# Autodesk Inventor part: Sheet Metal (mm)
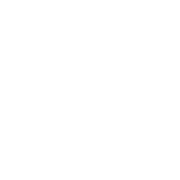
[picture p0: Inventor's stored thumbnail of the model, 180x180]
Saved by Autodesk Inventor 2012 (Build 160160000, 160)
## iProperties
Shininess: 64.0
Length Units: 11269
Angle Units: 11279
Time Units: 11290
Mass Units: 11283
Length Display Precision: 3
Angle Display Precision: 2
Compacted: True
Part Number: Sheet Metal (mm)
Document SubType Name: Sheet Metal
Created: 2002-07
Density: 1 g/cm^3
Sheet Metal Rule: Default
Material: Default
Density: 0.0
Volumn: 0.0
Area: 0.0
PropertySet Name: Model Information
Control State: 0
Master: False
Checked Out: False
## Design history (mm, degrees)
other parameters: "Thickness" = 0.5, "BendRadius" = 0.5 (= Thickness), "BendReliefWidth" = 0.5 (= Thickness), "BendReliefDepth" = 0.25 (= 0.5 x Thickness), "CornerReliefSize" = 2 (= 4 x Thickness), "SeamGap" = 0.01, "MinimumRemnant" = 1 (= 2 x Thickness), "TransitionRadius" = 0.5 (= BendRadius), "JacobiRadiusSize" = 0.5 (= BendRadius), "GapSize" = 0.5 (= Thickness)
